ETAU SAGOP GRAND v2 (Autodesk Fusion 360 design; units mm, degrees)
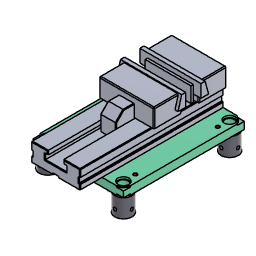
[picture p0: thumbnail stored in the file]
base_feature "Base Feature1"
base_feature "Base Feature1"
as_built_joint "As-built1"
as_built_joint "As-built2"
base_feature "Base Feature1"
as_built_joint "As-built1"
work_plane "WorkPlane1" User Parameter 50 named "Ouverture" User Parameter 8 named "epaisseurcale" User Parameter 50 named "hauteurcale"
sketch "Sketch1" plane through (0, -141, 48) normal (1, 0, 0) x axis (0, 1, 0)
  line L1 (141, 63) -> (133, 63)
  line L2 (141, 13) -> (141, 63)
  line L3 (133, 13) -> (141, 13)
  line L4 (133, 63) -> (133, 13)
  line L5 (-233, 13) -> (233, 13)
  line L6 (141, 78) -> (141, 36)
  point P2 (133, 63)
  point P3 (141, 63)
  point P5 (133, 13)
  horizontal L1
  vertical L2
  horizontal L3
  vertical L4
  collinear L3 L5
  collinear L2 L6
  dimension "d4" distance P2 P3 = 8 (= "epaisseurcale")
  dimension "d5" distance P2 P5 = 50 (= "hauteurcale")
extrude "Extrude1" add sketch "Sketch1" profile of L1 L2 L3 L4 distance 150
sketch "Sketch1" plane through (0, -141, 48) normal (1, 0, 0) x axis (0, 1, 0)
  line L1 (49, 63) -> (41, 63)
  line L2 (49, 13) -> (49, 63)
  line L3 (41, 13) -> (49, 13)
  line L4 (41, 63) -> (41, 13)
  line L5 (41, 36) -> (41, 78)
  line L6 (-233, 13) -> (147, 13)
  point P2 (41, 63)
  point P3 (49, 63)
  point P4 (49, 13)
  horizontal L1
  vertical L2
  horizontal L3
  vertical L4
  collinear L4 L5
  collinear L3 L6
  dimension "d8" distance P2 P3 = 8 (= "epaisseurcale")
  dimension "d9" distance P3 P4 = 50 (= "hauteurcale")
extrude "Extrude1" new body sketch "Sketch1" profile of L1 L2 L3 L4 distance 150
as_built_joint "As-built3"
ground "Ground1"
as_built_joint "As-built2"
joint "Assemble1" alignOffsetX 0 alignOffsetY 0 alignOffsetZ 50 (= "Ouverture")
base_feature "Fonction de base"
position "Position1"
delete_face "DeleteFace1"
rectangular_pattern "00000000-0000-0000-0000-000000000000" uSpaceDistance -348 vSpaceDistance 248
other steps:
create_component "CreateComponent1"
create_component "CreateComponent1"
create_component "CreateComponent2"
create_component "CreateComponent2"
create_component "CreateComponent1"
joint_origin "JointOrigin1" OffsetX 0 OffsetY 0 OffsetZ 0
joint_origin "JointOrigin1" OffsetX 0 OffsetY 0 OffsetZ 0
create_component "CreateComponent3"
